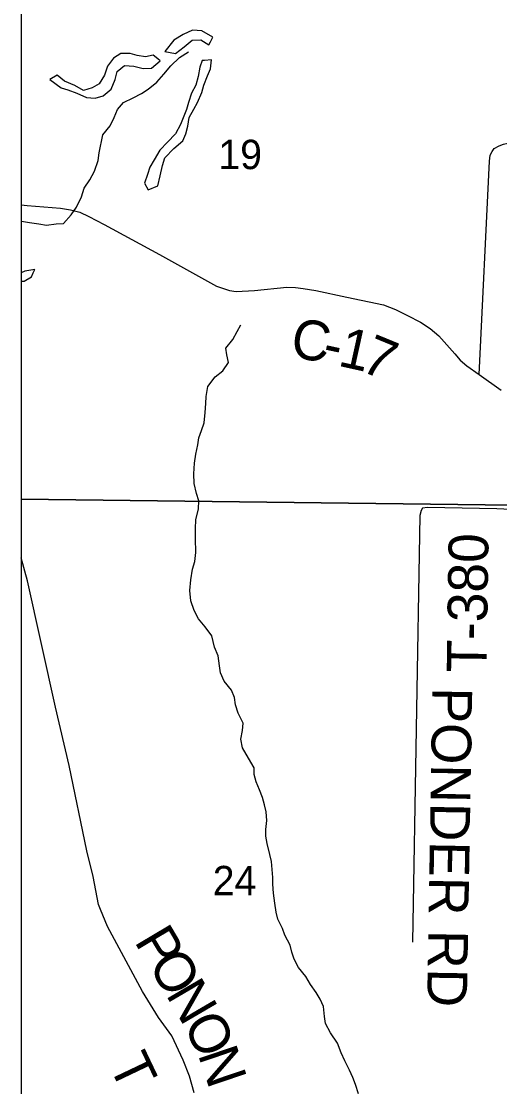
# Model space of a CAD drawing. Extents: x -3.6 to 34, y 0 to 32.8.
# Drawn here: x -3.63 to -2.947, y 28.286 to 29.806 of the extents above; entities that cross this region are included whole.
import ezdxf

# ---------------------------------------------------------------- set-up
doc = ezdxf.new("R2010")
doc.units = 0
for name, color, linetype in [('GM_X_Corporation', 7, 'Continuous'), ('GM_X_County_Road', 7, 'Continuous'), ('GM_X_County_Road_Text', 7, 'Continuous'), ('GM_X_Minor_Lake', 7, 'Continuous'), ('GM_X_Minor_River', 7, 'Continuous'), ('GM_X_Section_Text', 7, 'Continuous'), ('GM_X_Township_Road', 7, 'Continuous'), ('GM_X_Township_Road_Text', 7, 'Continuous'), ('SH_Data', 7, 'Continuous')]:
    doc.layers.add(name, color=color, linetype=linetype)

msp = doc.modelspace()

# ---------------------------------------------------------------- linework, layer by layer
at = {"layer": 'GM_X_Corporation'}
for points in [[(3.1705, 28.9337), (3.1705, 32.8429), (-3.6295, 32.8429), (-3.6295, 26.0429), (2.3706, 26.0429), (2.3712, 26.0804), (2.3716, 26.1248), (2.3732, 26.2253), (2.3789, 26.6097), (2.3911, 27.5117), (2.3952, 27.9336), (2.3997, 28.282), (2.4082, 28.9473), (2.5416, 28.945), (2.5837, 28.9442), (2.8343, 28.9397)], [(-3.6295, 30.6462), (-3.6295, 26.0429), (-2.8635, 26.0429), (-2.8499, 26.4099), (-2.8426, 27.1), (-2.8208, 28.0589), (-2.813, 28.9119), (-2.8073, 29.6484), (-2.8047, 30.129), (-2.8012, 30.524), (-2.8007, 30.6338), (-3.5736, 30.6453)], [(-3.6295, 30.1386), (-3.6295, 29.124), (-2.8121, 29.1143), (-2.8032, 30.1329)], [(-3.6295, 29.124), (-3.6295, 28.0641), (-2.8264, 28.0607), (-2.8121, 29.1143)]]:
    msp.add_lwpolyline(points, close=True, dxfattribs=at)
at = {"layer": 'GM_X_County_Road'}
msp.add_lwpolyline([(-3.6295, 29.5438), (-3.6212, 29.5428), (-3.5734, 29.5393), (-3.5592, 29.5368), (-3.5462, 29.5334), (-3.5331, 29.5272), (-3.5111, 29.5157), (-3.4325, 29.4732), (-3.3508, 29.428), (-3.3408, 29.4245), (-3.3322, 29.4217), (-3.323, 29.4203), (-3.2968, 29.4216), (-3.2505, 29.4267), (-3.2384, 29.426), (-3.2272, 29.4247), (-3.2091, 29.422), (-3.1649, 29.4125), (-3.1127, 29.4011), (-3.0957, 29.3947), (-3.0782, 29.386), (-3.06, 29.3766), (-3.046, 29.3674), (-3.0337, 29.3571), (-3.011, 29.3314), (-3.0032, 29.3225), (-2.9937, 29.3144), (-2.976, 29.3021), (-2.9446, 29.2795)], dxfattribs=at)
at = {"layer": 'GM_X_Minor_Lake'}
for points in [[(-3.3596, 29.7764), (-3.356, 29.7832), (-3.3721, 29.7921), (-3.3854, 29.7933), (-3.3985, 29.7867), (-3.412, 29.7789), (-3.4248, 29.7627)], [(-3.4248, 29.7627), (-3.4094, 29.7596), (-3.3971, 29.7693), (-3.3855, 29.7789), (-3.3734, 29.7795), (-3.3619, 29.7721), (-3.3596, 29.7764)], [(-3.4347, 29.7523), (-3.4412, 29.7575), (-3.4521, 29.7551), (-3.4642, 29.7571), (-3.4741, 29.7596), (-3.4874, 29.7598), (-3.4979, 29.7532), (-3.5064, 29.7416), (-3.5107, 29.7287), (-3.5184, 29.7164), (-3.5282, 29.711), (-3.5406, 29.707), (-3.5532, 29.7143), (-3.5677, 29.7201), (-3.5784, 29.7287), (-3.5886, 29.7228)], [(-3.5886, 29.7228), (-3.5728, 29.711), (-3.563, 29.7081), (-3.5504, 29.7034), (-3.5363, 29.6972), (-3.5241, 29.6959), (-3.5128, 29.6995), (-3.5013, 29.7091), (-3.4954, 29.7225), (-3.4926, 29.7339), (-3.4822, 29.7428), (-3.4689, 29.7415), (-3.4556, 29.7383), (-3.4439, 29.7389), (-3.4312, 29.7494), (-3.4347, 29.7523)], [(-3.368, 29.7499), (-3.3714, 29.7496), (-3.3746, 29.7401), (-3.377, 29.7268), (-3.3806, 29.7146), (-3.3865, 29.7031), (-3.3908, 29.6898), (-3.3936, 29.6799), (-3.3987, 29.668), (-3.4023, 29.6585), (-3.4093, 29.6451), (-3.4208, 29.6335), (-3.4316, 29.622), (-3.4397, 29.6082), (-3.4463, 29.5975), (-3.4496, 29.5872), (-3.4535, 29.575), (-3.4484, 29.5652)], [(-3.4484, 29.5652), (-3.4345, 29.5711), (-3.4314, 29.5852), (-3.4282, 29.6001), (-3.4246, 29.6111), (-3.4116, 29.6242), (-3.3989, 29.6354), (-3.3949, 29.6454), (-3.3917, 29.656), (-3.39, 29.6686), (-3.3834, 29.6804), (-3.3779, 29.69), (-3.3721, 29.7041), (-3.3692, 29.7144), (-3.3638, 29.7278), (-3.3594, 29.7381), (-3.3581, 29.7506), (-3.368, 29.7499)], [(-3.6125, 29.447), (-3.6104, 29.4518), (-3.6247, 29.4493), (-3.6295, 29.447)], [(-3.6295, 29.4349), (-3.6253, 29.4353), (-3.6148, 29.4415), (-3.6125, 29.447)]]:
    msp.add_lwpolyline(points, dxfattribs=at)
at = {"layer": 'GM_X_Minor_River'}
for points in [[(-3.6295, 29.5208), (-3.629, 29.5209), (-3.6176, 29.5188), (-3.6047, 29.5167), (-3.5937, 29.515), (-3.5797, 29.5168), (-3.5691, 29.5173), (-3.5584, 29.5296), (-3.5506, 29.5408), (-3.5437, 29.5553), (-3.5397, 29.5679), (-3.5316, 29.5797), (-3.525, 29.592), (-3.52, 29.6072), (-3.5186, 29.6179), (-3.513, 29.6437), (-3.5026, 29.6568), (-3.4968, 29.6683), (-3.4924, 29.6797), (-3.4835, 29.6897), (-3.47, 29.6964), (-3.458, 29.7027), (-3.4483, 29.7089), (-3.4363, 29.7189), (-3.4263, 29.7301), (-3.4159, 29.742), (-3.4036, 29.754), (-3.3909, 29.7622)], [(-3.3237, 28.8308), (-3.3254, 28.8414), (-3.3294, 28.852), (-3.3398, 28.8647), (-3.345, 28.8763), (-3.3467, 28.8866), (-3.3484, 28.9005), (-3.3539, 28.913), (-3.3576, 28.9292), (-3.3669, 28.9423), (-3.3766, 28.9535), (-3.3828, 28.9655), (-3.3876, 28.9791), (-3.389, 28.9939), (-3.3878, 29.0091), (-3.385, 29.0243), (-3.3818, 29.0353), (-3.3805, 29.0482), (-3.3808, 29.0679), (-3.3807, 29.0823), (-3.3805, 29.0948), (-3.3766, 29.1104), (-3.3761, 29.1218), (-3.3797, 29.1324), (-3.3829, 29.1467), (-3.3832, 29.1604), (-3.3823, 29.1755), (-3.3802, 29.1885), (-3.3778, 29.2018), (-3.3761, 29.2117), (-3.3725, 29.222), (-3.3685, 29.233), (-3.3673, 29.2478), (-3.366, 29.2604), (-3.3658, 29.2706), (-3.3634, 29.285), (-3.353, 29.2985), (-3.3418, 29.307), (-3.334, 29.3193), (-3.3361, 29.3298), (-3.3374, 29.3397), (-3.3278, 29.352), (-3.3215, 29.3635), (-3.316, 29.373)], [(-3.1484, 28.2762), (-3.1524, 28.2894), (-3.1564, 28.2995), (-3.1611, 28.3097), (-3.1678, 28.3232), (-3.1729, 28.3345), (-3.1784, 28.3481), (-3.1881, 28.3631), (-3.1956, 28.3766), (-3.1969, 28.3864), (-3.1983, 28.4008), (-3.203, 28.411), (-3.2088, 28.4207), (-3.2166, 28.432), (-3.2236, 28.4436), (-3.234, 28.4563), (-3.2403, 28.468), (-3.2435, 28.4781), (-3.2459, 28.488), (-3.2534, 28.5022), (-3.2569, 28.512), (-3.2632, 28.5252), (-3.2657, 28.535), (-3.2678, 28.5479), (-3.2695, 28.5622), (-3.2705, 28.5751), (-3.2707, 28.5846), (-3.2713, 28.5959), (-3.2726, 28.6073), (-3.2747, 28.6175), (-3.2787, 28.633), (-3.2804, 28.6436), (-3.2806, 28.653), (-3.2793, 28.6659), (-3.2799, 28.6781), (-3.2823, 28.6883), (-3.2855, 28.6988), (-3.2895, 28.7094), (-3.2942, 28.721), (-3.2974, 28.7316), (-3.2972, 28.7411), (-3.3054, 28.755), (-3.3136, 28.7696), (-3.3161, 28.7817), (-3.3136, 28.7942), (-3.3127, 28.8049), (-3.3201, 28.8188), (-3.3237, 28.8308)]]:
    msp.add_lwpolyline(points, dxfattribs=at)
at = {"layer": 'GM_X_Township_Road'}
for points in [[(-2.976, 29.3021), (-2.9613, 29.6061), (-2.9604, 29.615), (-2.9576, 29.6199), (-2.9545, 29.6241), (-2.9475, 29.6281), (-2.9412, 29.6307), (-2.9024, 29.6397), (-2.8319, 29.6537), (-2.8184, 29.6519), (-2.8127, 29.6499)], [(-2.9005, 29.1079), (-2.951, 29.1106), (-3.0499, 29.1125), (-3.0568, 29.1112), (-3.059, 29.1081), (-3.0606, 29.1009), (-3.0714, 28.4922)], [(-3.3826, 28.2777), (-3.3897, 28.3013), (-3.3983, 28.3243), (-3.4147, 28.3587), (-3.4335, 28.3848), (-3.4565, 28.4218), (-3.5064, 28.5149), (-3.5165, 28.5391), (-3.5192, 28.5462), (-3.527, 28.5861), (-3.5359, 28.6224), (-3.5614, 28.7441), (-3.5807, 28.8275), (-3.6209, 29.0075), (-3.6295, 29.0405)]]:
    msp.add_lwpolyline(points, dxfattribs=at)
at = {"layer": 'SH_Data'}
msp.add_line((-3.6295, 32.8429), (-3.6295, 26.0429), dxfattribs=at)

# ---------------------------------------------------------------- texts
at = {"layer": 'GM_X_County_Road_Text'}
for s, rotation, p in [('C', 350.4382, (-3.2473, 29.3274)), ('1', 347.5694, (-3.1792, 29.3148)), ('7', 337.6511, (-3.1475, 29.3081)), ('-', 347.8404, (-3.2019, 29.3197))]:
    msp.add_text(s, height=0.0568, rotation=rotation, dxfattribs=at).set_placement(p)
at = {"layer": 'GM_X_Section_Text'}
for s, p in [('19', (-3.3483, 29.5949)), ('24', (-3.3563, 28.5593))]:
    msp.add_text(s, height=0.04186, rotation=0, dxfattribs=at).set_placement(p)
at = {"layer": 'GM_X_Township_Road_Text'}
for s, height, rotation, p in [('T-380', 0.05682, 89.1569, (-2.9656, 28.8767)), ('PONDER RD', 0.05682, 269.0249, (-3.0427, 28.8561)), ('P', 0.0568, 300.7356, (-3.4691, 28.4937)), ('O', 0.0568, 300.738, (-3.4495, 28.4608)), ('N', 0.0568, 300.3106, (-3.424, 28.4179)), ('O', 0.0568, 296.2515, (-3.3993, 28.3757)), ('T', 0.0568, 295.4687, (-3.5053, 28.3178)), ('N', 0.0568, 288.697, (-3.3779, 28.3326))]:
    msp.add_text(s, height=height, rotation=rotation, dxfattribs=at).set_placement(p)

doc.saveas('drawing.dxf')
